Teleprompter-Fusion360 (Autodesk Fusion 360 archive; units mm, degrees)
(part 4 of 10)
sketch "Skizze46" plane through (0, 0, 0) normal (0, 0, -1) x axis (1, 0, 0)
  line L1 (47.0031, -126.3404) -> (155.5031, -126.3404)
  line L2 (35.0031, -31.3404) -> (35.0031, -114.3404)
  line L3 (155.5031, -19.3404) -> (47.0031, -19.3404)
  line L4 (167.5031, -114.3404) -> (167.5031, -31.3404)
  line L5 (71.0031, -202.3404) -> (155.5031, -202.3404)
  line L6 (59.0031, -174.3404) -> (59.0031, -190.3404)
  line L7 (155.5031, -162.3404) -> (71.0031, -162.3404)
  line L8 (167.5031, -190.3404) -> (167.5031, -174.3404)
  line L9 (191.5031, -31.3404) -> (191.5031, -114.3404)
  line L10 (312.0031, -19.3404) -> (203.5031, -19.3404)
  line L11 (324.0031, -114.3404) -> (324.0031, -31.3404)
  line L12 (203.5031, -126.3404) -> (312.0031, -126.3404)
  line L13 (300.0031, -190.3404) -> (300.0031, -174.3404)
  line L14 (203.5031, -202.3404) -> (288.0031, -202.3404)
  line L15 (191.5031, -174.3404) -> (191.5031, -190.3404)
  line L16 (288.0031, -162.3404) -> (203.5031, -162.3404)
  line L17 (-2.9969, -240.1877) -> (-2.9969, -130.1404)
  line L18 (-14.9969, -240.1877) -> (-2.9969, -240.1877)
  line L19 (-14.9969, -255.3404) -> (-14.9969, -240.1877)
  line L20 (374.0031, -255.3404) -> (-14.9969, -255.3404)
  line L21 (374.0031, -240.1877) -> (374.0031, -255.3404)
  line L22 (362.0031, -240.1877) -> (374.0031, -240.1877)
  line L23 (362.0031, -217.9972) -> (362.0031, -240.1877)
  line L24 (358.0031, -174.3404) -> (358.0031, -212.3404)
  line L25 (362.0031, -130.1404) -> (362.0031, -168.6835)
  line L26 (374.0031, -130.1404) -> (362.0031, -130.1404)
  line L27 (374.0031, -95.9404) -> (374.0031, -130.1404)
  line L28 (362.0031, -95.9404) -> (374.0031, -95.9404)
  line L29 (362.0031, -61.7404) -> (362.0031, -95.9404)
  line L30 (374.0031, -61.7404) -> (362.0031, -61.7404)
  line L31 (374.0031, -27.5404) -> (374.0031, -61.7404)
  line L32 (362.0031, -27.5404) -> (374.0031, -27.5404)
  line L33 (362.0031, 6.6596) -> (362.0031, -27.5404)
  line L34 (374.0031, 6.6596) -> (362.0031, 6.6596)
  line L35 (-2.9969, 18.6596) -> (362.0031, 18.6596)
  line L36 (-2.9969, 6.6596) -> (-14.9969, 6.6596)
  line L37 (-2.9969, -27.5404) -> (-2.9969, 6.6596)
  line L38 (-14.9969, -27.5404) -> (-2.9969, -27.5404)
  line L39 (-14.9969, -61.7404) -> (-14.9969, -27.5404)
  line L40 (-2.9969, -61.7404) -> (-14.9969, -61.7404)
  line L41 (-2.9969, -95.9404) -> (-2.9969, -61.7404)
  line L42 (-14.9969, -95.9404) -> (-2.9969, -95.9404)
  line L43 (-14.9969, -130.1404) -> (-14.9969, -95.9404)
  line L44 (-2.9969, -130.1404) -> (-14.9969, -130.1404)
  line L45 (364.1244, 4.5383) -> (362.0031, 6.6596)
  line L46 (365.0031, 6.6596) -> (362.0031, 6.6596)
  line L47 (364.1244, -25.4191) -> (362.0031, -27.5404)
  line L48 (365.0031, -27.5404) -> (362.0031, -27.5404)
  line L49 (364.1244, -63.8617) -> (362.0031, -61.7404)
  line L50 (365.0031, -61.7404) -> (362.0031, -61.7404)
  line L51 (364.1244, -93.8191) -> (362.0031, -95.9404)
  line L52 (365.0031, -95.9404) -> (362.0031, -95.9404)
  line L53 (364.1244, -132.2617) -> (362.0031, -130.1404)
  line L54 (365.0031, -130.1404) -> (362.0031, -130.1404)
  line L55 (364.1244, -238.0664) -> (362.0031, -240.1877)
  line L56 (365.0031, -240.1877) -> (362.0031, -240.1877)
  line L57 (-5.1183, -238.0664) -> (-2.9969, -240.1877)
  line L58 (0.0031, -240.1877) -> (-2.9969, -240.1877)
  line L59 (-5.1183, -132.2617) -> (-2.9969, -130.1404)
  line L60 (0.0031, -130.1404) -> (-2.9969, -130.1404)
  line L61 (-5.1183, -93.8191) -> (-2.9969, -95.9404)
  line L62 (0.0031, -95.9404) -> (-2.9969, -95.9404)
  line L63 (-5.1183, -63.8617) -> (-2.9969, -61.7404)
  line L64 (0.0031, -61.7404) -> (-2.9969, -61.7404)
  line L65 (-5.1183, -25.4191) -> (-2.9969, -27.5404)
  line L66 (0.0031, -27.5404) -> (-2.9969, -27.5404)
  line L67 (-5.1183, 4.5383) -> (-2.9969, 6.6596)
  line L68 (0.0031, 6.6596) -> (-2.9969, 6.6596)
  circle C1 centre (-8.9969, -113.0404) radius 1.5
  circle C2 centre (368.0031, -113.0404) radius 1.5
  arc A1 centre (47.0031, -114.3404) radius 12 clockwise from (47.0031, -126.3404) to (35.0031, -114.3404)
  arc A2 centre (47.0031, -31.3404) radius 12 clockwise from (35.0031, -31.3404) to (47.0031, -19.3404)
  arc A3 centre (155.5031, -31.3404) radius 12 clockwise from (155.5031, -19.3404) to (167.5031, -31.3404)
  arc A4 centre (155.5031, -114.3404) radius 12 clockwise from (167.5031, -114.3404) to (155.5031, -126.3404)
  arc A5 centre (71.0031, -190.3404) radius 12 clockwise from (71.0031, -202.3404) to (59.0031, -190.3404)
  arc A6 centre (71.0031, -174.3404) radius 12 clockwise from (59.0031, -174.3404) to (71.0031, -162.3404)
  arc A7 centre (155.5031, -174.3404) radius 12 clockwise from (155.5031, -162.3404) to (167.5031, -174.3404)
  arc A8 centre (155.5031, -190.3404) radius 12 clockwise from (167.5031, -190.3404) to (155.5031, -202.3404)
  arc A9 centre (203.5031, -31.3404) radius 12 clockwise from (191.5031, -31.3404) to (203.5031, -19.3404)
  arc A10 centre (312.0031, -31.3404) radius 12 clockwise from (312.0031, -19.3404) to (324.0031, -31.3404)
  arc A11 centre (312.0031, -114.3404) radius 12 clockwise from (324.0031, -114.3404) to (312.0031, -126.3404)
  arc A12 centre (203.5031, -114.3404) radius 12 clockwise from (203.5031, -126.3404) to (191.5031, -114.3404)
  arc A13 centre (288.0031, -190.3404) radius 12 clockwise from (300.0031, -190.3404) to (288.0031, -202.3404)
  arc A14 centre (203.5031, -190.3404) radius 12 clockwise from (203.5031, -202.3404) to (191.5031, -190.3404)
  arc A15 centre (203.5031, -174.3404) radius 12 clockwise from (191.5031, -174.3404) to (203.5031, -162.3404)
  arc A16 centre (288.0031, -174.3404) radius 12 clockwise from (288.0031, -162.3404) to (300.0031, -174.3404)
  arc A17 centre (364.0031, -212.3404) radius 6 clockwise from (362.0031, -217.9972) to (358.0031, -212.3404)
  arc A18 centre (364.0031, -174.3404) radius 6 clockwise from (358.0031, -174.3404) to (362.0031, -168.6835)
  arc A19 centre (362.0031, 6.6596) radius 12 clockwise from (362.0031, 18.6596) to (374.0031, 6.6596)
  arc A20 centre (-2.9969, 6.6596) radius 12 clockwise from (-14.9969, 6.6596) to (-2.9969, 18.6596)
  circle C3 centre (-5.1183, 4.5383) radius 3
  circle C4 centre (-5.1183, -25.4191) radius 3
  circle C5 centre (-5.1183, -63.8617) radius 3
  circle C6 centre (-5.1183, -93.8191) radius 3
  circle C7 centre (-5.1183, -132.2617) radius 3
  circle C8 centre (-5.1183, -238.0664) radius 3
  circle C9 centre (364.1244, -238.0664) radius 3
  circle C10 centre (364.1244, -132.2617) radius 3
  circle C11 centre (364.1244, -93.8191) radius 3
  circle C12 centre (364.1244, -63.8617) radius 3
  circle C13 centre (364.1244, 4.5383) radius 3
  circle C14 centre (364.1244, -25.4191) radius 3
  point P73 (362.0031, 6.6596)
  point P86 (362.0031, 6.6596)
  point P72 (362.0031, -27.5404)
  point P89 (362.0031, -27.5404)
  point P69 (362.0031, -61.7404)
  point P92 (362.0031, -61.7404)
  point P68 (362.0031, -95.9404)
  point P95 (362.0031, -95.9404)
  point P65 (362.0031, -130.1404)
  point P98 (362.0031, -130.1404)
  point P58 (362.0031, -240.1877)
  point P101 (362.0031, -240.1877)
  point P53 (-2.9969, -240.1877)
  point P104 (-2.9969, -240.1877)
  point P52 (-2.9969, -130.1404)
  point P107 (-2.9969, -130.1404)
  point P83 (-2.9969, -95.9404)
  point P110 (-2.9969, -95.9404)
  point P82 (-2.9969, -61.7404)
  point P113 (-2.9969, -61.7404)
  point P79 (-2.9969, -27.5404)
  point P116 (-2.9969, -27.5404)
  point P78 (-2.9969, 6.6596)
  point P119 (-2.9969, 6.6596)
  point P120 (-5.1183, 4.5383)
  point P122 (-5.1183, 4.5383)
  point P117 (-5.1183, -25.4191)
  point P123 (-5.1183, -25.4191)
  point P114 (-5.1183, -63.8617)
  point P124 (-5.1183, -63.8617)
  point P111 (-5.1183, -93.8191)
  point P125 (-5.1183, -93.8191)
  point P108 (-5.1183, -132.2617)
  point P126 (-5.1183, -132.2617)
  point P105 (-5.1183, -238.0664)
  point P127 (-5.1183, -238.0664)
  point P102 (364.1244, -238.0664)
  point P128 (364.1244, -238.0664)
  point P99 (364.1244, -132.2617)
  point P129 (364.1244, -132.2617)
  point P96 (364.1244, -93.8191)
  point P130 (364.1244, -93.8191)
  point P93 (364.1244, -63.8617)
  point P131 (364.1244, -63.8617)
  point P87 (364.1244, 4.5383)
  point P132 (364.1244, 4.5383)
  point P90 (364.1244, -25.4191)
  point P133 (364.1244, -25.4191)
  horizontal L46
  coincident P73 P86
  horizontal L48
  coincident P72 P89
  horizontal L50
  coincident P69 P92
  horizontal L52
  coincident P68 P95
  horizontal L54
  coincident P65 P98
  horizontal L56
  coincident P58 P101
  horizontal L58
  coincident P53 P104
  horizontal L60
  coincident P52 P107
  horizontal L62
  coincident P83 P110
  horizontal L64
  coincident P82 P113
  horizontal L66
  coincident P79 P116
  horizontal L68
  coincident P78 P119
  coincident P120 P122
  coincident P78 C3
  coincident P117 P123
  coincident P116 C4
  coincident P114 P124
  coincident P113 C5
  coincident P111 P125
  coincident P83 C6
  coincident P108 P126
  coincident P107 C7
  coincident P105 P127
  coincident P53 C8
  coincident P102 P128
  coincident P101 C9
  coincident P99 P129
  coincident P98 C10
  coincident P96 P130
  coincident P95 C11
  coincident P93 P131
  coincident P92 C12
  coincident P87 P132
  coincident P73 C13
  coincident P90 P133
  coincident P72 C14
  dimension "d253" angle L45 L46 = 45
  dimension "d254" distance P86 P87 = 3
  dimension "d255" angle L47 L48 = 45
  dimension "d256" distance P89 P90 = 3
  dimension "d257" angle L49 L50 = 45
  dimension "d258" distance P92 P93 = 3
  dimension "d259" angle L51 L52 = 45
  dimension "d260" distance P95 P96 = 3
  dimension "d261" angle L53 L54 = 45
  dimension "d262" distance P98 P99 = 3
  dimension "d263" angle L55 L56 = 45
  dimension "d264" distance P101 P102 = 3
  dimension "d265" angle L57 L58 = 135
  dimension "d266" distance P104 P105 = 3
  dimension "d267" angle L59 L60 = 135
  dimension "d268" distance P107 P108 = 3
  dimension "d269" angle L61 L62 = 135
  dimension "d270" distance P110 P111 = 3
  dimension "d271" angle L63 L64 = 135
  dimension "d272" distance P113 P114 = 3
  dimension "d273" angle L65 L66 = 135
  dimension "d274" distance P116 P117 = 3
  dimension "d275" angle L67 L68 = 135
  dimension "d276" distance P119 P120 = 3
extrude "Extrusion44" cut sketch "Skizze46" profile of L17 L18 L22 L23 L25 L26 L28 L29 L30 L32 L33 L34 L36 L37 L38 L40 L41 L42 L44 C3 C4 C5 C6 C7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 against normal blind 12
sketch "Skizze47" plane through (179.5031, 118.3404, 6) normal (1, 0, 0) x axis (0, 1, 0)
  line L1 (-90.8, -6) -> (-90.8, 6)
  line L2 (-90.8, 6) -> (-90.8, -6)
  line L3 (-125, 6) -> (-125, -6)
  line L4 (-125, -6) -> (-125, 6)
  line L5 (-123, 3) -> (-123, 6)
  line L6 (-123, 6) -> (-123, 3)
  line L7 (-4, 3) -> (-87, 3)
  line L8 (8, 3) -> (-4, 3)
  line L9 (8, 3) -> (-4, 3)
  line L10 (-87, 3) -> (-4, 3)
  line L11 (-87, 3) -> (-99, 3)
  line L12 (-87, 3) -> (-99, 3)
  line L13 (8, 3) -> (-4, 3)
  line L14 (-87, 3) -> (-4, 3)
  line L15 (-87, 3) -> (-99, 3)
  line L16 (-87, 3) -> (-99, 3)
  line L17 (-4, 3) -> (-87, 3)
  line L18 (8, 3) -> (-4, 3)
  line L19 (-118.5, 3) -> (32, 3)
  line L20 (-118.5, 3) -> (-123, 3)
  line L21 (-118.5, 3) -> (-123, 3)
  line L22 (32, 3) -> (-118.5, 3)
  line L23 (-56.6, 6) -> (-56.6, -6)
  line L24 (-56.6, -6) -> (-56.6, 6)
  line L25 (-22.4, -6) -> (-22.4, 6)
  line L26 (-22.4, 6) -> (-22.4, -6)
  line L27 (11.8, 6) -> (11.8, -6)
  line L28 (11.8, -6) -> (11.8, 6)
  line L29 (11.8, -6) -> (-125, -6)
  line L30 (34.056, 6) -> (-125, 6)
  line L31 (32, 6) -> (32, 3)
  point P4 (-125, -6)
  point P21 (-125, -6)
  point P19 (11.8, -6)
  point P22 (11.8, -6)
  point P5 (-125, 6)
  point P23 (-125, 6)
  coincident P4 P21
  coincident P19 P22
  coincident P5 P23
  perpendicular L26 L30
extrude "Extrusion45" cut sketch "Skizze47" profile of L1 L2 L5 L6 L7 L10 L11 L12 L14 L15 L16 L17 L19 L20 L21 L22 L23 L24 L25 L26 L27 L28 L30 L31 along normal blind 210 and against normal blind 220
sketch "Skizze48" plane through (0, 0, 0) normal (0, 0, -1) x axis (1, 0, 0)
  line L1 (300.0031, -190.3404) -> (300.0031, -174.3404)
  line L2 (203.5031, -202.3404) -> (288.0031, -202.3404)
  line L3 (191.5031, -174.3404) -> (191.5031, -190.3404)
  line L4 (288.0031, -162.3404) -> (203.5031, -162.3404)
  line L5 (191.5031, -31.3404) -> (191.5031, -114.3404)
  line L6 (312.0031, -19.3404) -> (203.5031, -19.3404)
  line L7 (324.0031, -114.3404) -> (324.0031, -31.3404)
  line L8 (203.5031, -126.3404) -> (312.0031, -126.3404)
  line L9 (71.0031, -202.3404) -> (155.5031, -202.3404)
  line L10 (59.0031, -174.3404) -> (59.0031, -190.3404)
  line L11 (155.5031, -162.3404) -> (71.0031, -162.3404)
  line L12 (167.5031, -190.3404) -> (167.5031, -174.3404)
  line L13 (47.0031, -126.3404) -> (155.5031, -126.3404)
  line L14 (35.0031, -31.3404) -> (35.0031, -114.3404)
  line L15 (155.5031, -19.3404) -> (47.0031, -19.3404)
  line L16 (167.5031, -114.3404) -> (167.5031, -31.3404)
  line L17 (362.0031, -217.9972) -> (362.0031, -235.9451)
  line L18 (358.0031, -174.3404) -> (358.0031, -212.3404)
  line L19 (362.0031, -134.383) -> (362.0031, -168.6835)
  line L20 (374.0031, -130.1404) -> (366.2457, -130.1404)
  line L21 (374.0031, -95.9404) -> (374.0031, -130.1404)
  line L22 (366.2457, -95.9404) -> (374.0031, -95.9404)
  line L23 (362.0031, -65.983) -> (362.0031, -91.6977)
  line L24 (374.0031, -61.7404) -> (366.2457, -61.7404)
  line L25 (374.0031, -27.5404) -> (374.0031, -61.7404)
  line L26 (366.2457, -27.5404) -> (374.0031, -27.5404)
  line L27 (362.0031, 2.417) -> (362.0031, -23.2977)
  line L28 (374.0031, 6.6596) -> (366.2457, 6.6596)
  line L29 (-2.9969, 18.6596) -> (362.0031, 18.6596)
  line L30 (-7.2396, 6.6596) -> (-14.9969, 6.6596)
  line L31 (-2.9969, -23.2977) -> (-2.9969, 2.417)
  line L32 (-14.9969, -27.5404) -> (-7.2396, -27.5404)
  line L33 (-14.9969, -61.7404) -> (-14.9969, -27.5404)
  line L34 (-7.2396, -61.7404) -> (-14.9969, -61.7404)
  line L35 (-2.9969, -91.6977) -> (-2.9969, -65.983)
  line L36 (-14.9969, -95.9404) -> (-7.2396, -95.9404)
  line L37 (-14.9969, -130.1404) -> (-14.9969, -95.9404)
  line L38 (-7.2396, -130.1404) -> (-14.9969, -130.1404)
  line L39 (-2.9969, -235.9451) -> (-2.9969, -134.383)
  line L40 (-14.9969, -240.1877) -> (-7.2396, -240.1877)
  line L41 (-14.9969, -255.3404) -> (-14.9969, -240.1877)
  line L42 (374.0031, -255.3404) -> (-14.9969, -255.3404)
  line L43 (374.0031, -240.1877) -> (374.0031, -255.3404)
  line L44 (366.2457, -240.1877) -> (374.0031, -240.1877)
  line L45 (368.0031, -61.7404) -> (368.0031, -27.5404)
  line L46 (-8.9969, -61.7404) -> (-8.9969, -27.5404)
  arc A1 centre (288.0031, -190.3404) radius 12 clockwise from (300.0031, -190.3404) to (288.0031, -202.3404)
  arc A2 centre (203.5031, -190.3404) radius 12 clockwise from (203.5031, -202.3404) to (191.5031, -190.3404)
  arc A3 centre (203.5031, -174.3404) radius 12 clockwise from (191.5031, -174.3404) to (203.5031, -162.3404)
  arc A4 centre (288.0031, -174.3404) radius 12 clockwise from (288.0031, -162.3404) to (300.0031, -174.3404)
  arc A5 centre (203.5031, -31.3404) radius 12 clockwise from (191.5031, -31.3404) to (203.5031, -19.3404)
  arc A6 centre (312.0031, -31.3404) radius 12 clockwise from (312.0031, -19.3404) to (324.0031, -31.3404)
  arc A7 centre (312.0031, -114.3404) radius 12 clockwise from (324.0031, -114.3404) to (312.0031, -126.3404)
  arc A8 centre (203.5031, -114.3404) radius 12 clockwise from (203.5031, -126.3404) to (191.5031, -114.3404)
  arc A9 centre (71.0031, -190.3404) radius 12 clockwise from (71.0031, -202.3404) to (59.0031, -190.3404)
  arc A10 centre (71.0031, -174.3404) radius 12 clockwise from (59.0031, -174.3404) to (71.0031, -162.3404)
  arc A11 centre (155.5031, -174.3404) radius 12 clockwise from (155.5031, -162.3404) to (167.5031, -174.3404)
  arc A12 centre (155.5031, -190.3404) radius 12 clockwise from (167.5031, -190.3404) to (155.5031, -202.3404)
  arc A13 centre (47.0031, -114.3404) radius 12 clockwise from (47.0031, -126.3404) to (35.0031, -114.3404)
  arc A14 centre (47.0031, -31.3404) radius 12 clockwise from (35.0031, -31.3404) to (47.0031, -19.3404)
  arc A15 centre (155.5031, -31.3404) radius 12 clockwise from (155.5031, -19.3404) to (167.5031, -31.3404)
  arc A16 centre (155.5031, -114.3404) radius 12 clockwise from (167.5031, -114.3404) to (155.5031, -126.3404)
  circle C1 centre (368.0031, -113.0404) radius 1.5
  circle C2 centre (-8.9969, -113.0404) radius 1.5
  arc A17 centre (364.1244, -238.0664) radius 3 clockwise from (366.2457, -240.1877) to (362.0031, -235.9451)
  arc A18 centre (364.0031, -212.3404) radius 6 clockwise from (362.0031, -217.9972) to (358.0031, -212.3404)
  arc A19 centre (364.0031, -174.3404) radius 6 clockwise from (358.0031, -174.3404) to (362.0031, -168.6835)
  arc A20 centre (364.1244, -132.2617) radius 3 clockwise from (362.0031, -134.383) to (366.2457, -130.1404)
  arc A21 centre (364.1244, -93.8191) radius 3 clockwise from (366.2457, -95.9404) to (362.0031, -91.6977)
  arc A22 centre (364.1244, -63.8617) radius 3 clockwise from (362.0031, -65.983) to (366.2457, -61.7404)
  arc A23 centre (364.1244, -25.4191) radius 3 clockwise from (366.2457, -27.5404) to (362.0031, -23.2977)
  arc A24 centre (364.1244, 4.5383) radius 3 clockwise from (362.0031, 2.417) to (366.2457, 6.6596)
  arc A25 centre (362.0031, 6.6596) radius 12 clockwise from (362.0031, 18.6596) to (374.0031, 6.6596)
  arc A26 centre (-2.9969, 6.6596) radius 12 clockwise from (-14.9969, 6.6596) to (-2.9969, 18.6596)
  arc A27 centre (-5.1183, 4.5383) radius 3 clockwise from (-7.2396, 6.6596) to (-2.9969, 2.417)
  arc A28 centre (-5.1183, -25.4191) radius 3 clockwise from (-2.9969, -23.2977) to (-7.2396, -27.5404)
  arc A29 centre (-5.1183, -63.8617) radius 3 clockwise from (-7.2396, -61.7404) to (-2.9969, -65.983)
  arc A30 centre (-5.1183, -93.8191) radius 3 clockwise from (-2.9969, -91.6977) to (-7.2396, -95.9404)
  arc A31 centre (-5.1183, -132.2617) radius 3 clockwise from (-7.2396, -130.1404) to (-2.9969, -134.383)
  arc A32 centre (-5.1183, -238.0664) radius 3 clockwise from (-2.9969, -235.9451) to (-7.2396, -240.1877)
  circle C3 centre (368.0031, -44.6404) radius 1.5
  circle C4 centre (-8.9969, -44.6404) radius 1.5
  point P114 (368.0031, -61.7404)
  point P115 (368.0031, -27.5404)
  point P116 (-8.9969, -44.6404)
  point P117 (368.0031, -44.6404)
  point P118 (368.0031, -44.6404)
  point P119 (-8.9969, -44.6404)
  perpendicular L26 L45
  vertical L46
  coincident L24 P114
  coincident L26 P115
  midpoint L46 P116
  midpoint L45 P117
  coincident P117 P118
  coincident P116 P119
  dimension "d283" distance L25 L45 = 6
  dimension "d284" distance L33 L46 = 6
  dimension "d285" diameter C3 = 3
  dimension "d286" diameter C4 = 3
extrude "Extrusion46" cut sketch "Skizze48" profile of L45 L46 C3 C4 against normal blind 12
sketch "Skizze49" plane through (374.0031, 0, 0) normal (1, 0, 0) x axis (0, 1, 0)
  line L1 (137.2147, 129.8223) -> (176.4327, 90.6042)
  line L2 (133.7, 177.9426) -> (133.7, 138.3075)
  line L3 (195.6625, 104.4333) -> (156.4445, 183.2864)
  line L4 (97.7, 198.3075) -> (97.7, 235.8456)
  line L5 (36.2984, 230.7386) -> (77.2147, 189.8223)
  line L6 (86.6874, 247.805) -> (45.7711, 251.1832)
  line L7 (113.9426, 213.455) -> (117.4574, 213.455)
  line L8 (109.7, 240.7124) -> (109.7, 217.6976)
  line L9 (117.4574, 244.955) -> (113.9426, 244.955)
  line L10 (121.7, 217.6976) -> (121.7, 240.7124)
  line L11 (121.7, 154.6976) -> (121.7, 177.7124)
  line L12 (113.9426, 150.455) -> (117.4574, 150.455)
  line L13 (109.7, 177.7124) -> (109.7, 154.6976)
  line L14 (117.4574, 181.955) -> (113.9426, 181.955)
  line L15 (167.9537, 59.4853) -> (114.5768, 112.8622)
  line L16 (106.0916, 39) -> (159.4684, 39)
  line L17 (94.0916, 104.3769) -> (94.0916, 51)
  line L18 (255.037, 12) -> (244.4304, 12)
  line L19 (136.7133, 249.9055) -> (255.037, 12)
  line L20 (123.6681, 256.7925) -> (126.9563, 256.521)
  line L21
  line L22 (-14.6596, 267) -> (-0.4576, 267)
  line L23 (-18.6596, 251.0692) -> (-18.6596, 263)
  line L24 (66.5768, 160.8622) -> (-15.1449, 242.5839)
  line L25 (70.0916, 39) -> (70.0916, 152.3769)
  line L26 (5.3404, 27) -> (58.0916, 27)
  line L27 (-6.6596, 0) -> (-6.6596, 15)
  line L28 (27.5404, 0) -> (-6.6596, 0)
  line L29 (27.5404, 7.7574) -> (27.5404, 0)
  line L30 (57.4977, 12) -> (31.783, 12)
  line L31 (61.7404, 0) -> (61.7404, 7.7574)
  line L32 (95.9404, 0) -> (61.7404, 0)
  line L33 (95.9404, 7.7574) -> (95.9404, 0)
  line L34 (125.8977, 12) -> (100.183, 12)
  line L35 (130.1404, 0) -> (130.1404, 7.7574)
  line L36 (164.3404, 0) -> (130.1404, 0)
  line L37 (164.3404, 11.3932) -> (164.3404, 0)
  line L38 (214.6835, 16) -> (169.9972, 16)
  line L39 (220.3404, 0) -> (220.3404, 11.3932)
  line L40 (240.1877, 0) -> (220.3404, 0)
  line L41 (240.1877, 7.7574) -> (240.1877, 0)
  line L42 (126.3404, 9) -> (126.3404, 0)
  line L43 (126.3404, 0) -> (126.3404, 9)
  line L44 (150.3404, 4) -> (150.3404, 9)
  line L45 (150.3404, 9) -> (150.3404, 4)
  line L46 (150.3404, 4) -> (226.3404, 4)
  line L47 (168.6835, 4) -> (150.3404, 4)
  line L48 (174.3404, 4) -> (168.6835, 4)
  line L49 (212.3404, 4) -> (174.3404, 4)
  line L50 (212.3404, 4) -> (217.9972, 4)
  line L51 (226.3404, 4) -> (217.9972, 4)
  line L52 (202.3404, 4) -> (190.3404, 4)
  line L53 (174.3404, 4) -> (190.3404, 4)
  line L54 (174.3404, 4) -> (162.3404, 4)
  line L55 (174.3404, 4) -> (162.3404, 4)
  line L56 (190.3404, 4) -> (174.3404, 4)
  line L57 (202.3404, 4) -> (190.3404, 4)
  line L58 (174.3404, 4) -> (190.3404, 4)
  line L59 (174.3404, 4) -> (162.3404, 4)
  line L60 (174.3404, 4) -> (162.3404, 4)
  line L61 (190.3404, 4) -> (174.3404, 4)
  line L62 (202.3404, 4) -> (190.3404, 4)
  line L63 (202.3404, 4) -> (190.3404, 4)
  line L64 (43.1404, 0) -> (46.1404, 0)
  line L65 (43.1404, 0) -> (46.1404, 0)
  line L66 (190.3404, 0) -> (174.3404, 0)
  line L67 (190.3404, 0) -> (202.3404, 0)
  line L68 (190.3404, 0) -> (202.3404, 0)
  line L69 (174.3404, 0) -> (190.3404, 0)
  line L70 (162.3404, 0) -> (174.3404, 0)
  line L71 (162.3404, 0) -> (174.3404, 0)
  line L72 (31.3404, 0) -> (114.3404, 0)
  line L73 (19.3404, 0) -> (31.3404, 0)
  line L74 (19.3404, 0) -> (31.3404, 0)
  line L75 (114.3404, 0) -> (31.3404, 0)
  line L76 (114.3404, 0) -> (126.3404, 0)
  line L77 (114.3404, 0) -> (126.3404, 0)
  line L78 (190.3404, 0) -> (202.3404, 0)
  line L79 (174.3404, 0) -> (190.3404, 0)
  line L80 (162.3404, 0) -> (174.3404, 0)
  line L81 (162.3404, 0) -> (174.3404, 0)
  line L82 (190.3404, 0) -> (174.3404, 0)
  line L83 (190.3404, 0) -> (202.3404, 0)
  line L84 (114.3404, 0) -> (126.3404, 0)
  line L85 (31.3404, 0) -> (114.3404, 0)
  line L86 (19.3404, 0) -> (31.3404, 0)
  line L87 (19.3404, 0) -> (31.3404, 0)
  line L88 (114.3404, 0) -> (31.3404, 0)
  line L89 (114.3404, 0) -> (126.3404, 0)
  line L90 (111.5404, 0) -> (114.5404, 0)
  line L91 (111.5404, 0) -> (114.5404, 0)
  line L92 (235.9451, 0) -> (241.0664, 0)
  line L93 (217.9972, 0) -> (235.9451, 0)
  line L94
  line L95
  line L96 (174.3404, 0) -> (168.6835, 0)
  line L97 (134.383, 0) -> (168.6835, 0)
  line L98 (129.2617, 0) -> (134.383, 0)
  line L99 (95.9404, 0) -> (130.1404, 0)
  line L100 (91.6977, 0) -> (96.8191, 0)
  line L101 (65.983, 0) -> (91.6977, 0)
  line L102 (60.8617, 0) -> (65.983, 0)
  line L103 (27.5404, 0) -> (61.7404, 0)
  line L104 (23.2977, 0) -> (28.4191, 0)
  line L105 (-2.417, 0) -> (23.2977, 0)
  line L106 (-7.5383, 0) -> (-2.417, 0)
  line L107 (-18.6596, 0) -> (-6.6596, 0)
  line L108 (-18.6596, 0) -> (-6.6596, 0)
  line L109 (-7.5383, 0) -> (-2.417, 0)
  line L110 (23.2977, 0) -> (-2.417, 0)
  line L111 (23.2977, 0) -> (28.4191, 0)
  line L112 (61.7404, 0) -> (27.5404, 0)
  line L113 (60.8617, 0) -> (65.983, 0)
  line L114 (91.6977, 0) -> (65.983, 0)
  line L115 (91.6977, 0) -> (96.8191, 0)
  line L116 (130.1404, 0) -> (95.9404, 0)
  line L117 (129.2617, 0) -> (134.383, 0)
  line L118 (235.9451, 0) -> (134.383, 0)
  line L119 (235.9451, 0) -> (241.0664, 0)
  line L120 (255.3404, 0) -> (240.1877, 0)
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  point P168 (140.2404, 6)
  point P169 (140.2404, 6)
  coincident P168 P169
  dimension "d289" distance = 6
  dimension "d290" distance = 20.2
  dimension "d291" distance L35 P168 = 10.1
  dimension "d292" diameter = 3
extrude "Extrusion47" cut sketch "Skizze49" against normal blind 420
sketch "Skizze50" plane through (0, 0, 244.955) normal (0, 0, 1) x axis (-1, 0, 0)
  line L1 (14.9969, -121.7) -> (-374.0031, -121.7)
  line L2 (14.9969, -109.7) -> (14.9969, -121.7)
  line L3 (-374.0031, -109.7) -> (14.9969, -109.7)
  line L4 (-374.0031, -121.7) -> (-374.0031, -109.7)
  line L5 (2.9969, -0.5298) -> (2.9969, -121.7)
  line L6 (-362.0031, -0.5298) -> (-362.0031, -121.7)
extrude "Extrusion48" add sketch "Skizze50" profile of L1 L3 L5 L6 along normal blind 12
sketch "Skizze51" plane through (0, 109.7, 0) normal (0, -1, 0) x axis (1, 0, 0)
  line L1 (161.0025, 194.455) -> (161.0025, 189.955)
  line L2 (194.0025, 198.455) -> (165.0025, 198.455)
  line L3 (198.0025, 189.955) -> (198.0025, 194.455)
  line L4 (217.2525, 189.955) -> (198.0025, 189.955)
  line L5 (141.7525, 162.455) -> (217.2525, 162.455)
  line L6 (161.0025, 189.955) -> (141.7525, 189.955)
  line L7 (338.0031, 186.455) -> (338.0031, 220.955)
  line L8 (260.3891, 174.455) -> (326.0031, 174.455)
  line L9 (217.4038, 212.4697) -> (251.9038, 177.9697)
  line L10 (326.0031, 232.955) -> (225.8891, 232.955)
  line L11 (33.0031, 174.455) -> (98.617, 174.455)
  line L12 (21.0031, 220.955) -> (21.0031, 186.455)
  line L13 (133.117, 232.955) -> (33.0031, 232.955)
  line L14 (107.1023, 177.9697) -> (141.6023, 212.4697)
  line L15 (362.0031, 209.2124) -> (362.0031, 186.1976)
  line L16 (374.0031, 213.455) -> (366.2457, 213.455)
  line L17 (374.0031, 244.955) -> (374.0031, 213.455)
  line L18 (362.0031, 244.955) -> (374.0031, 244.955)
  line L19 (362.0031, 256.955) -> (362.0031, 244.955)
  line L20 (-2.9969, 256.955) -> (362.0031, 256.955)
  line L21 (-2.9969, 244.955) -> (-2.9969, 256.955)
  line L22 (-14.9969, 244.955) -> (-2.9969, 244.955)
  line L23 (-14.9969, 213.455) -> (-14.9969, 244.955)
  line L24 (-7.2396, 213.455) -> (-14.9969, 213.455)
  line L25 (-2.9969, 186.1976) -> (-2.9969, 209.2124)
  line L26 (-14.9969, 181.955) -> (-7.2396, 181.955)
  line L27 (-14.9969, 150.455) -> (-14.9969, 181.955)
  line L28 (374.0031, 150.455) -> (-14.9969, 150.455)
  line L29 (374.0031, 181.955) -> (374.0031, 150.455)
  line L30 (366.2457, 181.955) -> (374.0031, 181.955)
  line L31 (-5.1183, 247.0763) -> (-2.9969, 244.955)
  line L32 (0.0031, 244.955) -> (-2.9969, 244.955)
  line L33 (364.1244, 247.0763) -> (362.0031, 244.955)
  line L34 (365.0031, 244.955) -> (362.0031, 244.955)
  arc A1 centre (165.0025, 194.455) radius 4 clockwise from (161.0025, 194.455) to (165.0025, 198.455)
  arc A2 centre (194.0025, 194.455) radius 4 clockwise from (194.0025, 198.455) to (198.0025, 194.455)
  arc A3 centre (217.2525, 176.205) radius 13.75 clockwise from (217.2525, 189.955) to (217.2525, 162.455)
  arc A4 centre (141.7525, 176.205) radius 13.75 clockwise from (141.7525, 162.455) to (141.7525, 189.955)
  arc A5 centre (326.0031, 186.455) radius 12 clockwise from (338.0031, 186.455) to (326.0031, 174.455)
  arc A6 centre (260.3891, 186.455) radius 12 clockwise from (260.3891, 174.455) to (251.9038, 177.9697)
  arc A7 centre (225.8891, 220.955) radius 12 clockwise from (217.4038, 212.4697) to (225.8891, 232.955)
  arc A8 centre (326.0031, 220.955) radius 12 clockwise from (326.0031, 232.955) to (338.0031, 220.955)
  arc A9 centre (33.0031, 186.455) radius 12 clockwise from (33.0031, 174.455) to (21.0031, 186.455)
  arc A10 centre (33.0031, 220.955) radius 12 clockwise from (21.0031, 220.955) to (33.0031, 232.955)
  arc A11 centre (133.117, 220.955) radius 12 clockwise from (133.117, 232.955) to (141.6023, 212.4697)
  arc A12 centre (98.617, 186.455) radius 12 clockwise from (107.1023, 177.9697) to (98.617, 174.455)
  arc A13 centre (364.1244, 184.0763) radius 3 clockwise from (366.2457, 181.955) to (362.0031, 186.1976)
  arc A14 centre (364.1244, 211.3337) radius 3 clockwise from (362.0031, 209.2124) to (366.2457, 213.455)
  arc A15 centre (-5.1183, 211.3337) radius 3 clockwise from (-7.2396, 213.455) to (-2.9969, 209.2124)
  arc A16 centre (-5.1183, 184.0763) radius 3 clockwise from (-2.9969, 186.1976) to (-7.2396, 181.955)
  circle C1 centre (364.1244, 247.0763) radius 3
  circle C2 centre (-5.1183, 247.0763) radius 3
  point P51 (-2.9969, 244.955)
  point P64 (-2.9969, 244.955)
  point P48 (362.0031, 244.955)
  point P67 (362.0031, 244.955)
  point P68 (364.1244, 247.0763)
  point P70 (364.1244, 247.0763)
  point P65 (-5.1183, 247.0763)
  point P71 (-5.1183, 247.0763)
  horizontal L32
  coincident P51 P64
  horizontal L34
  coincident P48 P67
  coincident P68 P70
  coincident P67 C1
  coincident P65 P71
  coincident P64 C2
  dimension "d297" angle L31 L32 = 135
  dimension "d298" distance P64 P65 = 3
  dimension "d299" angle L33 L34 = 45
  dimension "d300" distance P67 P68 = 3
extrude "Extrusion49" cut sketch "Skizze51" profile of L18 L19 L21 L22 C1 C2 against normal blind 15
sketch "Skizze53" plane through (374.0031, 0, 0) normal (1, 0, 0) x axis (0, 1, 0)
  line L1 (137.2147, 129.8223) -> (176.4327, 90.6042)
  line L2 (133.7, 177.9426) -> (133.7, 138.3075)
  line L3 (195.6625, 104.4333) -> (156.4445, 183.2864)
  line L4 (97.7, 198.3075) -> (97.7, 235.8456)
  line L5 (36.2984, 230.7386) -> (77.2147, 189.8223)
  line L6 (86.6874, 247.805) -> (45.7711, 251.1832)
  line L7 (113.9426, 213.455) -> (117.4574, 213.455)
  line L8 (109.7, 240.7124) -> (109.7, 217.6976)
  line L9 (117.4574, 244.955) -> (113.9426, 244.955)
  line L10 (121.7, 217.6976) -> (121.7, 240.7124)
  line L11 (121.7, 154.6976) -> (121.7, 177.7124)
  line L12 (113.9426, 150.455) -> (117.4574, 150.455)
  line L13 (109.7, 177.7124) -> (109.7, 154.6976)
  line L14 (117.4574, 181.955) -> (113.9426, 181.955)
  line L15 (167.9537, 59.4853) -> (114.5768, 112.8622)
  line L16 (106.0916, 39) -> (159.4684, 39)
  line L17 (94.0916, 104.3769) -> (94.0916, 51)
  line L18 (255.037, 12) -> (244.4304, 12)
  line L19 (136.7133, 249.9055) -> (255.037, 12)
  line L20 (123.6681, 256.7925) -> (126.9563, 256.521)
  line L21
  line L22 (-14.6596, 267) -> (-0.4576, 267)
  line L23 (-18.6596, 251.0692) -> (-18.6596, 263)
  line L24 (66.5768, 160.8622) -> (-15.1449, 242.5839)
  line L25 (70.0916, 39) -> (70.0916, 152.3769)
  line L26 (5.3404, 27) -> (58.0916, 27)
  line L27 (-6.6596, 0) -> (-6.6596, 15)
  line L28 (27.5404, 0) -> (-6.6596, 0)
  line L29 (27.5404, 7.7574) -> (27.5404, 0)
  line L30 (57.4977, 12) -> (31.783, 12)
  line L31 (61.7404, 0) -> (61.7404, 7.7574)
  line L32 (95.9404, 0) -> (61.7404, 0)
  line L33 (95.9404, 7.7574) -> (95.9404, 0)
  line L34 (125.8977, 12) -> (100.183, 12)
  line L35 (130.1404, 0) -> (130.1404, 7.7574)
  line L36 (164.3404, 0) -> (130.1404, 0)
  line L37 (164.3404, 11.3932) -> (164.3404, 0)
  line L38 (214.6835, 16) -> (169.9972, 16)
  line L39 (220.3404, 0) -> (220.3404, 11.3932)
  line L40 (240.1877, 0) -> (220.3404, 0)
  line L41 (240.1877, 7.7574) -> (240.1877, 0)
  line L42 (240.1877, 0) -> (240.1877, 12)
  line L43 (255.3404, 0) -> (240.1877, 0)
  line L44 (255.3404, 12) -> (255.3404, 0)
  line L45 (240.1877, 12) -> (255.3404, 12)
  line L46 (255.3404, 0) -> (255.037, 12)
  line L47 (220.3404, 0) -> (255.3404, 0)
  line L48 (237.3593, 7.0503) -> (-18.6596, 263.0692)
  line L49 (-18.6596, 263.0692) -> (237.3593, 7.0503)
  line L50 (239.4113, 10.6551) -> (240.1877, 9.8787)
  line L51 (-15.8312, 265.8976) -> (239.4113, 10.6551)
  line L52 (240.1877, 9.8787) -> (-15.8312, 265.8976)
  line L53 (-18.6596, 263.0692) -> (-12.6141, 257.0237)
  circle C1 centre (140.2404, 6) radius 1.5
  circle C2 centre (115.7, 197.705) radius 1.5
  arc A1 centre (184.918, 99.0895) radius 12 clockwise from (195.6625, 104.4333) to (176.4327, 90.6042)
  arc A2 centre (145.7, 138.3075) radius 12 clockwise from (137.2147, 129.8223) to (133.7, 138.3075)
  arc A3 centre (145.7, 177.9426) radius 12 clockwise from (133.7, 177.9426) to (156.4445, 183.2864)
  arc A4 centre (85.7, 235.8456) radius 12 clockwise from (86.6874, 247.805) to (97.7, 235.8456)
  arc A5 centre (85.7, 198.3075) radius 12 clockwise from (97.7, 198.3075) to (77.2147, 189.8223)
  arc A6 centre (44.7837, 239.2239) radius 12 clockwise from (36.2984, 230.7386) to (45.7711, 251.1832)
  arc A7 centre (111.8213, 215.5763) radius 3 clockwise from (113.9426, 213.455) to (109.7, 217.6976)
  arc A8 centre (111.8213, 242.8337) radius 3 clockwise from (109.7, 240.7124) to (113.9426, 244.955)
  arc A9 centre (119.5787, 242.8337) radius 3 clockwise from (117.4574, 244.955) to (121.7, 240.7124)
  arc A10 centre (119.5787, 215.5763) radius 3 clockwise from (121.7, 217.6976) to (117.4574, 213.455)
  arc A11 centre (119.5787, 152.5763) radius 3 clockwise from (121.7, 154.6976) to (117.4574, 150.455)
  arc A12 centre (111.8213, 152.5763) radius 3 clockwise from (113.9426, 150.455) to (109.7, 154.6976)
  arc A13 centre (111.8213, 179.8337) radius 3 clockwise from (109.7, 177.7124) to (113.9426, 181.955)
  arc A14 centre (119.5787, 179.8337) radius 3 clockwise from (117.4574, 181.955) to (121.7, 177.7124)
  arc A15 centre (159.4684, 51) radius 12 clockwise from (167.9537, 59.4853) to (159.4684, 39)
  arc A16 centre (106.0916, 51) radius 12 clockwise from (106.0916, 39) to (94.0916, 51)
  arc A17 centre (106.0916, 104.3769) radius 12 clockwise from (94.0916, 104.3769) to (114.5768, 112.8622)
  circle C3 centre (230.2641, 6) radius 1.5
  circle C4 centre (10.4404, 6) radius 1.5
  circle C5 centre (78.8404, 6) radius 1.5
  arc A18 centre (242.3091, 9.8787) radius 3 clockwise from (240.1877, 7.7574) to (244.4304, 12)
  arc A19 centre (125.9689, 244.5617) radius 12 clockwise from (126.9563, 256.521) to (136.7133, 249.9055)
  arc A20 centre (121.7, 244.955) radius 12 clockwise from (121.7, 256.955) to (123.6681, 256.7925)
  arc A21 centre (-0.4576, 255) radius 12 clockwise from (-0.4576, 267) to (0.5298, 266.9593)
  arc A22 centre (-14.6596, 263) radius 4 clockwise from (-18.6596, 263) to (-14.6596, 267)
  arc A23 centre (-6.6596, 251.0692) radius 12 clockwise from (-15.1449, 242.5839) to (-18.6596, 251.0692)
  arc A24 centre (58.0916, 152.3769) radius 12 clockwise from (66.5768, 160.8622) to (70.0916, 152.3769)
  arc A25 centre (58.0916, 39) radius 12 clockwise from (70.0916, 39) to (58.0916, 27)
  arc A26 centre (5.3404, 15) radius 12 clockwise from (-6.6596, 15) to (5.3404, 27)
  arc A27 centre (29.6617, 9.8787) radius 3 clockwise from (27.5404, 7.7574) to (31.783, 12)
  arc A28 centre (59.6191, 9.8787) radius 3 clockwise from (57.4977, 12) to (61.7404, 7.7574)
  arc A29 centre (98.0617, 9.8787) radius 3 clockwise from (95.9404, 7.7574) to (100.183, 12)
  arc A30 centre (128.0191, 9.8787) radius 3 clockwise from (125.8977, 12) to (130.1404, 7.7574)
  arc A31 centre (167.3404, 11.3932) radius 3 clockwise from (164.3404, 11.3932) to (164.6835, 12.7865)
  arc A32 centre (169.9972, 10) radius 6 clockwise from (164.6835, 12.7865) to (169.9972, 16)
  arc A33 centre (214.6835, 10) radius 6 clockwise from (214.6835, 16) to (219.9972, 12.7865)
  arc A34 centre (217.3404, 11.3932) radius 3 clockwise from (219.9972, 12.7865) to (220.3404, 11.3932)
  point P61 (255.037, 12)
  point P120 (255.037, 12)
  point P118 (255.3404, 0)
  point P121 (255.3404, 0)
  point P114 (220.3404, 0)
  point P122 (220.3404, 0)
  point P128 (-12.6141, 257.0237)
  point P123 (-18.6596, 263.0692)
  point P129 (-18.6596, 263.0692)
  coincident P61 P120
  coincident P118 P121
  coincident P114 P122
  coincident L49 P128
  coincident P123 P129
  parallel L49 L53
sketch "Skizze55" plane through (0, 0, 0) normal (0, 0, -1) x axis (1, 0, 0)
  line L1 (300.0031, -190.3404) -> (300.0031, -174.3404)
  line L2 (203.5031, -202.3404) -> (288.0031, -202.3404)
  line L3 (191.5031, -174.3404) -> (191.5031, -190.3404)
  line L4 (288.0031, -162.3404) -> (203.5031, -162.3404)
  line L5 (191.5031, -31.3404) -> (191.5031, -114.3404)
  line L6 (312.0031, -19.3404) -> (203.5031, -19.3404)
  line L7 (324.0031, -114.3404) -> (324.0031, -31.3404)
  line L8 (203.5031, -126.3404) -> (312.0031, -126.3404)
  line L9 (71.0031, -202.3404) -> (155.5031, -202.3404)
  line L10 (59.0031, -174.3404) -> (59.0031, -190.3404)
  line L11 (155.5031, -162.3404) -> (71.0031, -162.3404)
  line L12 (167.5031, -190.3404) -> (167.5031, -174.3404)
  line L13 (47.0031, -126.3404) -> (155.5031, -126.3404)
  line L14 (35.0031, -31.3404) -> (35.0031, -114.3404)
  line L15 (155.5031, -19.3404) -> (47.0031, -19.3404)
  line L16 (167.5031, -114.3404) -> (167.5031, -31.3404)
  line L17 (362.0031, -217.9972) -> (362.0031, -235.9451)
  line L18 (358.0031, -174.3404) -> (358.0031, -212.3404)
  line L19 (362.0031, -134.383) -> (362.0031, -168.6835)
  line L20 (374.0031, -130.1404) -> (366.2457, -130.1404)
  line L21 (374.0031, -95.9404) -> (374.0031, -130.1404)
  line L22 (366.2457, -95.9404) -> (374.0031, -95.9404)
  line L23 (362.0031, -65.983) -> (362.0031, -91.6977)
  line L24 (374.0031, -61.7404) -> (366.2457, -61.7404)
  line L25 (374.0031, -27.5404) -> (374.0031, -61.7404)
  line L26 (366.2457, -27.5404) -> (374.0031, -27.5404)
  line L27 (362.0031, 2.417) -> (362.0031, -23.2977)
  line L28 (374.0031, 6.6596) -> (366.2457, 6.6596)
  line L29 (-2.9969, 18.6596) -> (362.0031, 18.6596)
  line L30 (-7.2396, 6.6596) -> (-14.9969, 6.6596)
  line L31 (-2.9969, -23.2977) -> (-2.9969, 2.417)
  line L32 (-14.9969, -27.5404) -> (-7.2396, -27.5404)
  line L33 (-14.9969, -61.7404) -> (-14.9969, -27.5404)
  line L34 (-7.2396, -61.7404) -> (-14.9969, -61.7404)
  line L35 (-2.9969, -91.6977) -> (-2.9969, -65.983)
  line L36 (-14.9969, -95.9404) -> (-7.2396, -95.9404)
  line L37 (-14.9969, -130.1404) -> (-14.9969, -95.9404)
  line L38 (-7.2396, -130.1404) -> (-14.9969, -130.1404)
  line L39 (-2.9969, -235.9451) -> (-2.9969, -134.383)
  line L40 (-14.9969, -240.1877) -> (-7.2396, -240.1877)
  line L41 (-14.9969, -255.3404) -> (-14.9969, -240.1877)
  line L42 (374.0031, -255.3404) -> (-14.9969, -255.3404)
  line L43 (374.0031, -240.1877) -> (374.0031, -255.3404)
  line L44 (366.2457, -240.1877) -> (374.0031, -240.1877)
  line L45 (-2.9969, -164.3404) -> (-14.9969, -164.3404)
  line L46 (-14.9969, -164.3404) -> (-2.9969, -164.3404)
  line L47 (-14.9969, -220.3404) -> (-2.9969, -220.3404)
  line L48 (-2.9969, -220.3404) -> (-14.9969, -220.3404)
  line L49 (32.2537, -220.3404) -> (-2.9969, -220.3404)
  line L50 (-2.9968, -164.3404) -> (-2.9969, -164.3404)
  line L51 (0.0031, -217.3404) -> (0.0031, -167.3404)
  line L52 (-2.9969, -220.3404) -> (-2.9968, -220.3404)
  line L53 (-2.9969, -164.3404) -> (-2.9969, -220.3404)
  line L54 (374.0031, -164.3404) -> (362.0031, -164.3404)
  line L55 (362.0031, -164.3404) -> (374.0031, -164.3404)
  line L56 (362.0031, -220.3404) -> (374.0031, -220.3404)
  line L57 (374.0031, -220.3404) -> (362.0031, -220.3404)
  line L58 (358.0031, -217.3404) -> (358.0031, -167.3404)
  line L59 (362.0031, -220.3404) -> (362.0031, -164.3404)
  line L60 (358.0031, -174.3404) -> (358.0031, -212.3404)
  line L61 (361.0031, -164.3404) -> (362.0031, -164.3404)
  line L62 (361.0031, -220.3404) -> (362.0031, -220.3404)
  circle C1 centre (-8.9969, -44.6404) radius 1.5
  circle C2 centre (368.0031, -44.6404) radius 1.5
  arc A1 centre (288.0031, -190.3404) radius 12 clockwise from (300.0031, -190.3404) to (288.0031, -202.3404)
  arc A2 centre (203.5031, -190.3404) radius 12 clockwise from (203.5031, -202.3404) to (191.5031, -190.3404)
  arc A3 centre (203.5031, -174.3404) radius 12 clockwise from (191.5031, -174.3404) to (203.5031, -162.3404)
  arc A4 centre (288.0031, -174.3404) radius 12 clockwise from (288.0031, -162.3404) to (300.0031, -174.3404)
  arc A5 centre (203.5031, -31.3404) radius 12 clockwise from (191.5031, -31.3404) to (203.5031, -19.3404)
  arc A6 centre (312.0031, -31.3404) radius 12 clockwise from (312.0031, -19.3404) to (324.0031, -31.3404)
  arc A7 centre (312.0031, -114.3404) radius 12 clockwise from (324.0031, -114.3404) to (312.0031, -126.3404)
  arc A8 centre (203.5031, -114.3404) radius 12 clockwise from (203.5031, -126.3404) to (191.5031, -114.3404)
  arc A9 centre (71.0031, -190.3404) radius 12 clockwise from (71.0031, -202.3404) to (59.0031, -190.3404)
  arc A10 centre (71.0031, -174.3404) radius 12 clockwise from (59.0031, -174.3404) to (71.0031, -162.3404)
  arc A11 centre (155.5031, -174.3404) radius 12 clockwise from (155.5031, -162.3404) to (167.5031, -174.3404)
  arc A12 centre (155.5031, -190.3404) radius 12 clockwise from (167.5031, -190.3404) to (155.5031, -202.3404)
  arc A13 centre (47.0031, -114.3404) radius 12 clockwise from (47.0031, -126.3404) to (35.0031, -114.3404)
  arc A14 centre (47.0031, -31.3404) radius 12 clockwise from (35.0031, -31.3404) to (47.0031, -19.3404)
  arc A15 centre (155.5031, -31.3404) radius 12 clockwise from (155.5031, -19.3404) to (167.5031, -31.3404)
  arc A16 centre (155.5031, -114.3404) radius 12 clockwise from (167.5031, -114.3404) to (155.5031, -126.3404)
  circle C3 centre (368.0031, -113.0404) radius 1.5
  circle C4 centre (-8.9969, -113.0404) radius 1.5
  arc A17 centre (364.1244, -238.0664) radius 3 clockwise from (366.2457, -240.1877) to (362.0031, -235.9451)
  arc A18 centre (364.0031, -212.3404) radius 6 clockwise from (362.0031, -217.9972) to (358.0031, -212.3404)
  arc A19 centre (364.0031, -174.3404) radius 6 clockwise from (358.0031, -174.3404) to (362.0031, -168.6835)
  arc A20 centre (364.1244, -132.2617) radius 3 clockwise from (362.0031, -134.383) to (366.2457, -130.1404)
  arc A21 centre (364.1244, -93.8191) radius 3 clockwise from (366.2457, -95.9404) to (362.0031, -91.6977)
  arc A22 centre (364.1244, -63.8617) radius 3 clockwise from (362.0031, -65.983) to (366.2457, -61.7404)
  arc A23 centre (364.1244, -25.4191) radius 3 clockwise from (366.2457, -27.5404) to (362.0031, -23.2977)
  arc A24 centre (364.1244, 4.5383) radius 3 clockwise from (362.0031, 2.417) to (366.2457, 6.6596)
  arc A25 centre (362.0031, 6.6596) radius 12 clockwise from (362.0031, 18.6596) to (374.0031, 6.6596)
  arc A26 centre (-2.9969, 6.6596) radius 12 clockwise from (-14.9969, 6.6596) to (-2.9969, 18.6596)
  arc A27 centre (-5.1183, 4.5383) radius 3 clockwise from (-7.2396, 6.6596) to (-2.9969, 2.417)
  arc A28 centre (-5.1183, -25.4191) radius 3 clockwise from (-2.9969, -23.2977) to (-7.2396, -27.5404)
  arc A29 centre (-5.1183, -63.8617) radius 3 clockwise from (-7.2396, -61.7404) to (-2.9969, -65.983)
  arc A30 centre (-5.1183, -93.8191) radius 3 clockwise from (-2.9969, -91.6977) to (-7.2396, -95.9404)
  arc A31 centre (-5.1183, -132.2617) radius 3 clockwise from (-7.2396, -130.1404) to (-2.9969, -134.383)
  arc A32 centre (-5.1183, -238.0664) radius 3 clockwise from (-2.9969, -235.9451) to (-7.2396, -240.1877)
  arc A33 centre (-2.9969, -167.3404) radius 3 clockwise from (-2.9968, -164.3404) to (0.0031, -167.3404)
  arc A34 centre (-2.9969, -217.3404) radius 3 clockwise from (0.0031, -217.3404) to (-2.9968, -220.3404)
  arc A35 centre (361.0031, -167.3404) radius 3 clockwise from (358.0031, -167.3404) to (361.0031, -164.3404)
  arc A36 centre (361.0031, -217.3404) radius 3 clockwise from (361.0031, -220.3404) to (358.0031, -217.3404)
  point P116 (-2.9969, -220.3404)
  point P118 (-2.9969, -220.3404)
  point P115 (-2.9969, -164.3404)
  point P120 (-2.9969, -164.3404)
  point P121 (0.0031, -164.3405)
  point P129 (362.0031, -164.3404)
  point P133 (362.0031, -164.3404)
  point P132 (362.0031, -220.3404)
  point P134 (362.0031, -220.3404)
  coincident P116 P118
  perpendicular L39 L49
  vertical L51
  vertical L53
  coincident P115 P120
  coincident P121 L50
  coincident P121 L51
  tangent L50 A33
  tangent L51 A33
  tangent L51 A34
  tangent L52 A34
  vertical L58
  coincident P129 P133
  coincident P132 P134
  perpendicular L59 L61
  perpendicular L17 L62
  tangent L61 A35
  tangent L58 A35
  tangent L62 A36
  tangent L58 A36
  dimension "d321" distance P120 P121 = 3
  dimension "d322" radius A33 = 3
  dimension "d323" radius A34 = 3
  dimension "d326" distance L59 L60 = 4
  dimension "d327" distance L58 L59 = 4
  dimension "d328" radius A35 = 3
  dimension "d329" radius A36 = 3
extrude "Extrusion55" cut sketch "Skizze55" profile of L17 A18 A19 L19 L39 L49 L50 L51 L52 L53 A33 A34 L58 L59 L61 L62 A35 A36 against normal blind 10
